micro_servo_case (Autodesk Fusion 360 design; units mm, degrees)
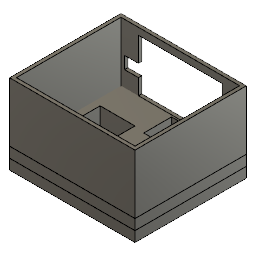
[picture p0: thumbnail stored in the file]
sketch "Sketch1" plane through (0, 0, 0) normal (0, 1, 0) x axis (1, 0, 0)
  line L1 (6, 10) -> (-30, 10)
  line L2 (6, -22) -> (6, 10)
  line L3 (-30, -22) -> (6, -22)
  line L4 (-30, 10) -> (-30, -22)
  line L5 (5, 9) -> (-29, 9)
  line L6 (5, -21) -> (5, 9)
  line L7 (-29, -21) -> (5, -21)
  line L8 (-29, 9) -> (-29, -21)
  point P2 (-30, 10)
  point P3 (6, 10)
  point P5 (-30, -22)
  dimension "d2" distance P2 P3 = 36
  dimension "d3" distance P2 P5 = 32
  dimension "d48" distance L5 L7 = 30
  dimension "d52" distance L6 L8 = 34
extrude "Extrude4" new body sketch "Sketch1" along normal blind 20
extrude "Extrude1" new body sketch "Sketch1" distance 3
sketch "Sketch3" plane through (0, 0, -9) normal (0, 0, 1) x axis (1, 0, 0)
  line L1 (5, 0) -> (-29, 0)
  line L2 (5, 20) -> (5, 0)
  line L3 (-29, 20) -> (5, 20)
  line L4 (-29, 0) -> (-29, 20)
  line L5 (0, 18) -> (-24, 18)
  line L6 (0, 3) -> (0, 18)
  line L7 (-24, 3) -> (0, 3)
  line L8 (-24, 18) -> (-24, 3)
extrude "Extrude5" cut sketch "Sketch3" profile of L5 L6 L7 L8 against normal blind 3
sketch "Sketch4" plane through (0, 3, 0) normal (0, 1, 0) x axis (-1, 0, 0)
  line L1 (-6, 22) -> (30, 22)
  line L2 (-6, -10) -> (-6, 22)
  line L3 (30, -10) -> (-6, -10)
  line L4 (30, 22) -> (30, -10)
  line L5 (6, -8.5) -> (14, -8.5)
  line L6 (6, -0.5) -> (6, -8.5)
  line L7 (14, -0.5) -> (6, -0.5)
  line L8 (14, -8.5) -> (14, -0.5)
  line L9 (6, 11.5) -> (14, 11.5)
  line L10 (6, 19.5) -> (6, 11.5)
  line L11 (14, 19.5) -> (6, 19.5)
  line L12 (14, 11.5) -> (14, 19.5)
  line L13 (-5, -9) -> (29, -9)
  line L14 (29, -9) -> (29, 21)
  line L15 (-5, 21) -> (-5, -9)
  line L16 (17, -1) -> (27, -1)
  line L17 (17, 10) -> (17, -1)
  line L18 (27, 10) -> (17, 10)
  line L19 (27, -1) -> (27, 10)
  circle C1 centre (10, -4.5) radius 1.75
  circle C2 centre (10, 15.5) radius 1.75
  point P10 (14, 11.5)
  point P11 (6, 11.5)
  point P14 (10, -4.5)
  point P15 (10, 15.5)
  point P22 (27, -1)
  point P23 (17, -1)
  point P25 (27, 10)
  dimension "d23" distance P10 P11 = 8
  dimension "d24" diameter C1 = 3.5
  dimension "d25" diameter C2 = 3.5
  dimension "d26" distance P14 P15 = 20
  dimension "d46" distance L9 L11 = 8
  dimension "d49" distance L5 L9 = 20
  dimension "d50" distance L5 L13 = 0.5
  dimension "d51" distance L5 P14 = 4
  dimension "d55" distance L14 L15 = 34
  dimension "d60" distance P22 P23 = 10
  dimension "d61" distance P22 P25 = 11
extrude "Extrude9" cut sketch "Sketch4" profile of L16 L17 L18 L19 against normal blind 10
extrude "Extrude7" cut sketch "Sketch4" profile of C1 C2 against normal blind 10
extrude "Extrude6" cut sketch "Sketch4" profile of L5 L6 L7 L8 L9 L10 L11 L12 C1 C2 against normal blind 3
thread "Thread1"
sketch "Sketch5" plane through (0, 0, -10) normal (0, 0, -1) x axis (-1, 0, 0)
  line L1 (0, 18) -> (0, 3)
  line L2 (24, 18) -> (0, 18)
  line L3 (24, 3) -> (24, 18)
  line L4 (0, 3) -> (24, 3)
  line L5 (30, 0) -> (-6, 0)
  line L6 (30, 20) -> (30, 0)
  line L7 (-6, 20) -> (30, 20)
  line L8 (-6, 0) -> (-6, 20)
  line L9 (-4, 11) -> (0, 11)
  line L10 (-4, 7.5) -> (-4, 11)
  line L11 (0, 7.5) -> (-4, 7.5)
  line L12 (0, 11) -> (0, 7.5)
  line L13 (-6, 0) -> (30, 0)
  line L14 (27.9737, 11) -> (23.9737, 11)
  line L15 (27.9737, 7.5) -> (27.9737, 11)
  line L16 (23.9737, 7.5) -> (27.9737, 7.5)
  line L17 (23.9737, 11) -> (23.9737, 7.5)
  dimension "d56" distance L9 L11 = 3.5
  dimension "d57" distance L14 L16 = 3.5
  dimension "d58" distance L7 L9 = 9
  dimension "d59" distance L7 L14 = 9
extrude "Extrude8" cut sketch "Sketch5" profile of L1 L3 L9 L10 L11 L12 L14 L15 L16 against normal blind 3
